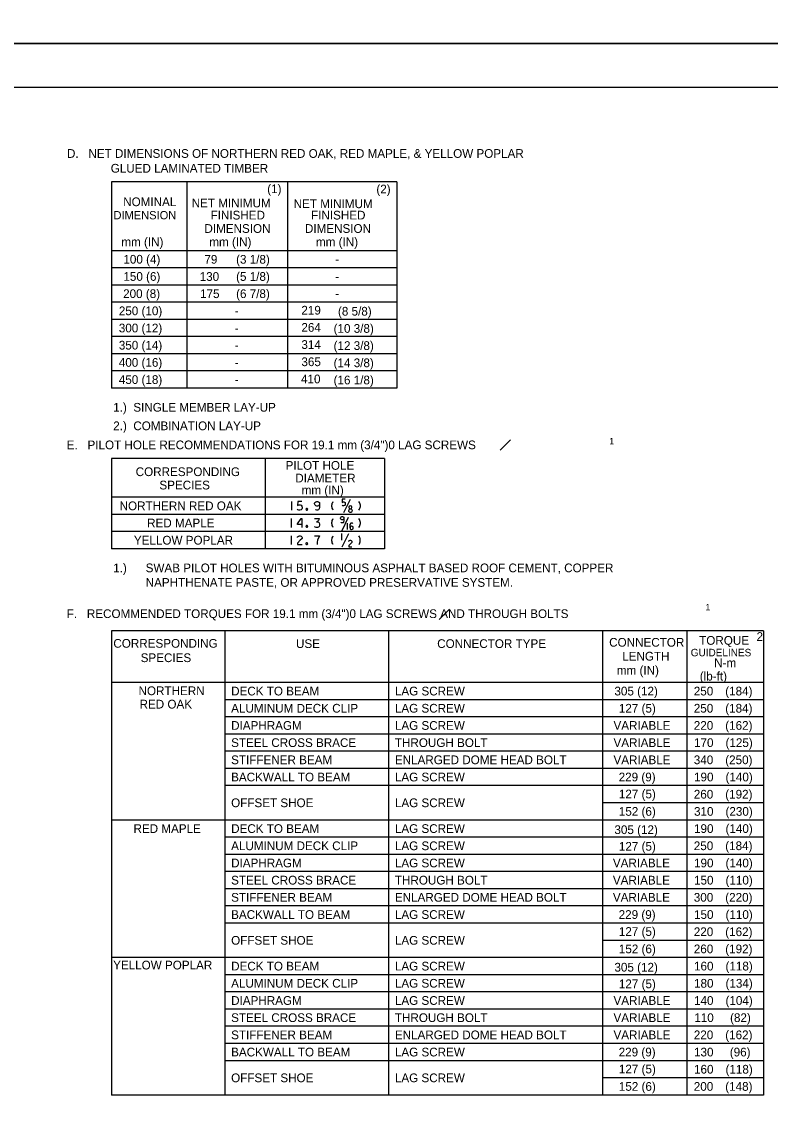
# Model space of a CAD drawing. Extents: x 637594 to 640253, y 297247 to 298527.
# Drawn here: x 639602.6 to 639860.2, y 297476.2 to 297849 of the extents above; entities that cross this region are included whole.
import ezdxf

# ---------------------------------------------------------------- set-up
doc = ezdxf.new("R2010")
doc.units = 0
doc.layers.add('2', color=7, linetype='Continuous')
doc.layers.add('PLT-BNDY', color=7, linetype='Continuous')

msp = doc.modelspace()

# ---------------------------------------------------------------- linework, layer by layer
at = {"layer": '2'}
for p, q in [((639316.46, 297826.46), (640102.46, 297826.46)), ((639731.6, 297793.9), (639633.44, 297793.9)), ((639633.44, 297793.9), (639633.44, 297722.88)), ((639659.42, 297793.9), (639659.42, 297722.88)), ((639694, 297793.9), (639694, 297722.88)), ((639731.6, 297793.9), (639731.6, 297722.88)), ((639659.42, 297787.92), (639659.42, 297746.53)), ((639731.6, 297770.18), (639633.44, 297770.18)), ((639731.6, 297764.27), (639633.44, 297764.27)), ((639731.6, 297758.36), (639633.44, 297758.36)), ((639731.6, 297752.45), (639633.44, 297752.45)), ((639731.6, 297746.53), (639633.44, 297746.53)), ((639731.6, 297740.62), (639633.44, 297740.62)), ((639731.6, 297734.71), (639633.44, 297734.71)), ((639731.6, 297728.8), (639633.44, 297728.8)), ((639731.6, 297722.88), (639633.44, 297722.88)), ((639770.79, 297705.12), (639767.24, 297701.57)), ((639727.37, 297698.69), (639633.44, 297698.69)), ((639633.44, 297698.69), (639633.44, 297667.64)), ((639686.39, 297698.69), (639686.39, 297667.64)), ((639727.37, 297698.69), (639727.37, 297667.64)), ((639727.37, 297685.38), (639633.44, 297685.38)), ((639727.37, 297679.47), (639633.44, 297679.47)), ((639727.37, 297673.55), (639633.44, 297673.55)), ((639727.37, 297667.64), (639633.44, 297667.64)), ((639749.76, 297646.92), (639746.21, 297643.37)), ((639857.76, 297639.39), (639633.44, 297639.39)), ((639633.44, 297639.39), (639633.44, 297479.75)), ((639672.46, 297639.39), (639672.46, 297479.75)), ((639728.79, 297639.39), (639728.79, 297479.75)), ((639802.42, 297639.39), (639802.42, 297479.75)), ((639831.43, 297639.39), (639831.43, 297479.75)), ((639857.76, 297639.39), (639857.76, 297479.75)), ((639857.76, 297621.65), (639633.44, 297621.65)), ((639857.76, 297615.74), (639672.46, 297615.74)), ((639857.76, 297609.83), (639672.46, 297609.83)), ((639857.76, 297603.91), (639672.46, 297603.91)), ((639857.76, 297598), (639672.46, 297598)), ((639857.76, 297592.09), (639672.46, 297592.09)), ((639857.76, 297586.18), (639672.46, 297586.18)), ((639857.76, 297580.26), (639802.42, 297580.26)), ((639857.76, 297574.35), (639633.44, 297574.35)), ((639857.76, 297568.44), (639672.46, 297568.44)), ((639857.76, 297562.53), (639672.46, 297562.53)), ((639857.76, 297556.61), (639672.46, 297556.61)), ((639857.76, 297550.7), (639672.46, 297550.7)), ((639857.76, 297544.79), (639672.46, 297544.79)), ((639857.76, 297538.87), (639672.46, 297538.87)), ((639857.76, 297532.96), (639802.42, 297532.96)), ((639857.76, 297527.05), (639633.44, 297527.05)), ((639857.76, 297521.14), (639672.46, 297521.14)), ((639857.76, 297515.22), (639672.46, 297515.22)), ((639857.76, 297509.31), (639672.46, 297509.31)), ((639857.76, 297503.4), (639672.46, 297503.4)), ((639857.76, 297497.48), (639672.46, 297497.48)), ((639857.76, 297491.57), (639672.46, 297491.57)), ((639857.76, 297485.66), (639802.42, 297485.66)), ((639857.76, 297479.75), (639633.44, 297479.75))]:
    msp.add_line(p, q, dxfattribs=at)
for points in [[(639695.46, 297680.92), (639695.46, 297683.92)], [(639699, 297683.92), (639697.53, 297683.92), (639697.42, 297682.5), (639697.98, 297682.76), (639698.39, 297682.76), (639698.76, 297682.62), (639699, 297682.36), (639699.12, 297682.01), (639699.12, 297681.63), (639699, 297681.25), (639698.76, 297681.01), (639698.24, 297680.92), (639697.89, 297680.92), (639697.63, 297681.01), (639697.42, 297681.27)], [(639705.09, 297682.83), (639704.72, 297682.46), (639704.34, 297682.31), (639704.1, 297682.29), (639703.75, 297682.46), (639703.49, 297682.69), (639703.37, 297683.07), (639703.37, 297683.19), (639703.46, 297683.59), (639703.72, 297683.8), (639704.1, 297683.92), (639704.34, 297683.92), (639704.69, 297683.8), (639704.98, 297683.59), (639705.09, 297683.19), (639705.09, 297682.31), (639705.05, 297682.01), (639704.95, 297681.35), (639704.83, 297681.13), (639704.69, 297681.01), (639704.34, 297680.92), (639704.1, 297680.92), (639703.75, 297681.01), (639703.6, 297681.13)], [(639709.77, 297680.92), (639709.58, 297681.23), (639709.44, 297681.56), (639709.35, 297681.89), (639709.3, 297682.24), (639709.3, 297682.6), (639709.35, 297682.95), (639709.44, 297683.28), (639709.58, 297683.61), (639709.77, 297683.92)], [(639713.83, 297684.68), (639712.87, 297684.68), (639712.79, 297683.61), (639713.17, 297683.83), (639713.43, 297683.83), (639713.69, 297683.71), (639713.83, 297683.52), (639713.91, 297683.26), (639713.91, 297682.97), (639713.83, 297682.69), (639713.69, 297682.5), (639713.34, 297682.43), (639713.1, 297682.43), (639712.94, 297682.5), (639712.79, 297682.69)], [(639713.41, 297680.16), (639715.65, 297684.68)], [(639718.62, 297680.92), (639718.81, 297681.23), (639718.95, 297681.56), (639719.04, 297681.89), (639719.09, 297682.24), (639719.09, 297682.6), (639719.04, 297682.95), (639718.95, 297683.28), (639718.81, 297683.61), (639718.62, 297683.92)], [(639700.98, 297681.23), (639700.96, 297681.35), (639700.89, 297681.44), (639700.79, 297681.51), (639700.68, 297681.53), (639700.56, 297681.51), (639700.46, 297681.44), (639700.39, 297681.35), (639700.37, 297681.23), (639700.39, 297681.11), (639700.46, 297681.01), (639700.56, 297680.94), (639700.68, 297680.92), (639700.79, 297680.94), (639700.89, 297681.01), (639700.96, 297681.11), (639700.98, 297681.23)], [(639715.8, 297681.42), (639716.01, 297681.49), (639716.1, 297681.61), (639716.15, 297681.87), (639716.15, 297681.98), (639716.1, 297682.27), (639715.98, 297682.34), (639715.68, 297682.41), (639715.35, 297682.34), (639715.28, 297682.27), (639715.18, 297681.98), (639715.18, 297681.87), (639715.25, 297681.61), (639715.35, 297681.49), (639715.58, 297681.42), (639715.8, 297681.42), (639716.01, 297681.27), (639716.15, 297681.06), (639716.25, 297680.83), (639716.25, 297680.73), (639716.17, 297680.42), (639716.01, 297680.23), (639715.8, 297680.16), (639715.58, 297680.16), (639715.35, 297680.23), (639715.18, 297680.42), (639715.13, 297680.71), (639715.13, 297680.83), (639715.21, 297681.06), (639715.35, 297681.27), (639715.58, 297681.42)], [(639695.45, 297675.01), (639695.45, 297678.01)], [(639699.12, 297676.05), (639697.42, 297676.05), (639697.42, 297676.17), (639698.74, 297678.01), (639698.9, 297678.01), (639698.9, 297675.01)], [(639703.37, 297678.01), (639704.95, 297678.01), (639704.86, 297677.65), (639704.69, 297677.39), (639704.46, 297677.16), (639703.98, 297676.92), (639704.34, 297676.92), (639704.71, 297676.76), (639704.95, 297676.52), (639705.07, 297676.14), (639705.07, 297675.74), (639704.95, 297675.34), (639704.69, 297675.1), (639704.34, 297675.01), (639703.93, 297675.01), (639703.58, 297675.1), (639703.37, 297675.36)], [(639709.77, 297675.01), (639709.58, 297675.31), (639709.44, 297675.64), (639709.34, 297675.98), (639709.3, 297676.33), (639709.3, 297676.68), (639709.34, 297677.04), (639709.44, 297677.37), (639709.58, 297677.7), (639709.77, 297678.01)], [(639713.43, 297677.96), (639713.2, 297677.68), (639712.93, 297677.56), (639712.77, 297677.56), (639712.53, 297677.68), (639712.37, 297677.84), (639712.3, 297678.13), (639712.3, 297678.22), (639712.37, 297678.53), (639712.53, 297678.69), (639712.77, 297678.76), (639712.93, 297678.76), (639713.17, 297678.69), (639713.36, 297678.53), (639713.43, 297678.22), (639713.43, 297677.56), (639713.38, 297677.35), (639713.34, 297676.85), (639713.27, 297676.68), (639713.17, 297676.59), (639712.93, 297676.52), (639712.77, 297676.52), (639712.53, 297676.59), (639712.46, 297676.68)], [(639712.82, 297673.97), (639715.04, 297678.48)], [(639714.71, 297674.25), (639714.71, 297676.49)], [(639716.5, 297676.35), (639716.41, 297676.42), (639716.22, 297676.49), (639716.03, 297676.49), (639715.79, 297676.42), (639715.51, 297676.05), (639715.46, 297675.69), (639715.46, 297675.29), (639715.49, 297674.96), (639715.63, 297674.51), (639715.79, 297674.32), (639716.03, 297674.25), (639716.43, 297674.35), (639716.6, 297674.51), (639716.67, 297674.79), (639716.67, 297674.94), (639716.6, 297675.15), (639716.43, 297675.36), (639716.17, 297675.43), (639716.01, 297675.46), (639715.77, 297675.36), (639715.63, 297675.15), (639715.53, 297674.79)], [(639718.62, 297675.01), (639718.8, 297675.31), (639718.95, 297675.64), (639719.04, 297675.98), (639719.09, 297676.33), (639719.09, 297676.68), (639719.04, 297677.04), (639718.95, 297677.37), (639718.8, 297677.7), (639718.62, 297678.01)], [(639695.45, 297669.09), (639695.45, 297672.09)], [(639697.41, 297671.48), (639697.5, 297671.76), (639697.76, 297672), (639698.12, 297672.09), (639698.38, 297672.09), (639698.73, 297672), (639698.99, 297671.74), (639699.11, 297671.48), (639699.11, 297671.22), (639699.01, 297671.01), (639698.42, 297670.56), (639697.5, 297669.61), (639697.41, 297669.38), (639697.41, 297669.09), (639699.11, 297669.09)], [(639700.98, 297675.31), (639700.96, 297675.43), (639700.89, 297675.53), (639700.79, 297675.6), (639700.67, 297675.62), (639700.56, 297675.6), (639700.46, 297675.53), (639700.39, 297675.43), (639700.37, 297675.31), (639700.39, 297675.2), (639700.46, 297675.1), (639700.56, 297675.03), (639700.67, 297675.01), (639700.79, 297675.03), (639700.89, 297675.1), (639700.96, 297675.2), (639700.98, 297675.31)], [(639703.36, 297672.09), (639705.06, 297672.09), (639705.06, 297671.98), (639704.54, 297671.22), (639704.33, 297670.63), (639704.21, 297669.9), (639704.21, 297669.09)], [(639709.76, 297669.09), (639709.57, 297669.4), (639709.43, 297669.73), (639709.34, 297670.06), (639709.29, 297670.42), (639709.29, 297670.77), (639709.34, 297671.13), (639709.43, 297671.46), (639709.57, 297671.79), (639709.76, 297672.09)], [(639712.76, 297670.61), (639712.76, 297672.85)], [(639712.86, 297668.34), (639715.1, 297672.85)], [(639718.61, 297669.09), (639718.8, 297669.4), (639718.94, 297669.73), (639719.03, 297670.06), (639719.08, 297670.42), (639719.08, 297670.77), (639719.03, 297671.13), (639718.94, 297671.46), (639718.8, 297671.79), (639718.61, 297672.09)], [(639700.97, 297669.4), (639700.95, 297669.52), (639700.88, 297669.61), (639700.78, 297669.68), (639700.67, 297669.71), (639700.55, 297669.68), (639700.45, 297669.61), (639700.38, 297669.52), (639700.36, 297669.4), (639700.38, 297669.28), (639700.45, 297669.19), (639700.55, 297669.12), (639700.67, 297669.09), (639700.78, 297669.12), (639700.88, 297669.19), (639700.95, 297669.28), (639700.97, 297669.4)], [(639715.1, 297670.13), (639715.15, 297670.35), (639715.31, 297670.51), (639715.57, 297670.58), (639715.74, 297670.58), (639715.97, 297670.51), (639716.14, 297670.32), (639716.21, 297670.13), (639716.21, 297669.94), (639716.14, 297669.78), (639715.76, 297669.45), (639715.15, 297668.74), (639715.1, 297668.55), (639715.1, 297668.34), (639716.21, 297668.34)]]:
    msp.add_lwpolyline(points, dxfattribs=at)
at = {"layer": 'PLT-BNDY'}
for points in [[(639276.46, 298435.46), (640117.46, 298435.46), (640117.46, 297841.46), (639276.46, 297841.46)], [(639276.46, 297841.46), (640117.46, 297841.46), (640117.46, 297247.46), (639276.46, 297247.46)]]:
    msp.add_lwpolyline(points, close=True, dxfattribs=at)

# ---------------------------------------------------------------- texts
at = {"layer": '2'}
for s, height, p in [('D.   NET DIMENSIONS OF NORTHERN RED OAK, RED MAPLE, & YELLOW POPLAR', 3.0001, (639618.16, 297802.12)), ('GLUED LAMINATED TIMBER', 3.0001, (639633.2, 297797.03)), ('(1)', 3, (639687.05, 297789.97)), ('(2)', 3, (639724.6, 297789.88)), ('NOMINAL', 3, (639637.5, 297785.5)), ('NET MINIMUM', 3.0001, (639661.06, 297785.08)), ('NET MINIMUM', 3.0001, (639696.15, 297784.82)), ('FINISHED', 3, (639667.55, 297780.91)), ('FINISHED', 3, (639702.13, 297780.91)), ('DIMENSION', 2.85, (639634.15, 297780.97)), ('DIMENSION', 3, (639665.44, 297776.31)), ('DIMENSION', 3, (639700.02, 297776.31)), ('mm (IN)', 3, (639636.85, 297771.72)), ('mm (IN)', 3, (639667.12, 297771.72)), ('mm (IN)', 3, (639703.82, 297771.72)), ('100 (4)', 3, (639637.56, 297765.73)), ('79', 3, (639665.43, 297765.71)), ('(3 1/8)', 3, (639676.34, 297765.71)), ('-', 3, (639710.43, 297765.73)), ('150 (6)', 3, (639637.56, 297759.82)), ('130', 3, (639663.81, 297759.8)), ('(5 1/8)', 3, (639676.34, 297759.8)), ('-', 3, (639710.43, 297759.82)), ('200 (8)', 3, (639637.47, 297753.9)), ('175', 3, (639663.94, 297753.89)), ('(6 7/8)', 3, (639676.34, 297753.89)), ('-', 3, (639710.43, 297753.9)), ('250 (10)', 3, (639635.99, 297747.99)), ('219', 3, (639698.8, 297748.21)), ('(8 5/8)', 3, (639711.39, 297747.85)), ('-', 3, (639675.85, 297747.99)), ('300 (12)', 3, (639635.99, 297742.08)), ('-', 3, (639675.85, 297742.08)), ('264', 3, (639698.81, 297742.3)), ('(10 3/8)', 3, (639709.89, 297741.94)), ('350 (14)', 3, (639635.99, 297736.17)), ('314', 3, (639698.81, 297736.39)), ('(12 3/8)', 3, (639709.89, 297736.03)), ('-', 3, (639675.85, 297736.17)), ('400 (16)', 3, (639635.99, 297730.25)), ('365', 3, (639698.81, 297730.47)), ('(14 3/8)', 3, (639709.89, 297730.11)), ('-', 3, (639675.85, 297730.25)), ('450 (18)', 3, (639635.99, 297724.34)), ('-', 3, (639675.85, 297724.34)), ('410', 3, (639698.68, 297724.56)), ('(16 1/8)', 3, (639709.89, 297724.2)), ('1.)  SINGLE MEMBER LAY-UP', 3.0001, (639634.06, 297714.81)), ('2.)  COMBINATION LAY-UP', 3.0001, (639634.06, 297708.44)), ('1', 2.25, (639804.72, 297703.55)), ('E.   PILOT HOLE RECOMMENDATIONS FOR 19.1 mm (3/4")0 LAG SCREWS', 3.0001, (639618.08, 297701.88)), ('CORRESPONDING', 3.0001, (639641.79, 297692.65)), ('PILOT HOLE', 3, (639693.36, 297694.82)), ('SPECIES', 3, (639649.94, 297688.06)), ('DIAMETER', 3, (639696.71, 297690.46)), ('mm (IN)', 3, (639698.89, 297686.36)), ('NORTHERN RED OAK', 3.0001, (639636.26, 297680.92)), ('RED MAPLE', 3, (639645.72, 297675.01)), ('YELLOW POPLAR', 3.0001, (639641.17, 297669.1)), ('1.)', 3, (639634.06, 297659.57)), ('SWAB PILOT HOLES WITH BITUMINOUS ASPHALT BASED ROOF CEMENT, COPPER', 3.0001, (639645.22, 297659.57)), ('NAPHTHENATE PASTE, OR APPROVED PRESERVATIVE SYSTEM.', 3.0001, (639645.22, 297654.57)), ('F.   RECOMMENDED TORQUES FOR 19.1 mm (3/4")0 LAG SCREWS AND THROUGH BOLTS', 3.0001, (639618.08, 297643.82)), ('1', 2.25, (639837.83, 297646.42)), ('2', 3, (639855.4, 297635.95)), ('CORRESPONDING', 3.0001, (639634.11, 297633.61)), ('USE', 3, (639696.95, 297633.52)), ('CONNECTOR TYPE', 3.0001, (639745.53, 297633.52)), ('CONNECTOR', 3, (639804.7, 297633.97)), ('TORQUE', 3, (639835.67, 297634.63)), ('SPECIES', 3, (639643.5, 297628.67)), ('LENGTH', 3, (639809.19, 297629.19)), ('GUIDELINES', 2.572, (639832.76, 297630.66)), ('mm (IN)', 3, (639807.34, 297624.34)), ('N-m', 3, (639840.84, 297626.91)), ('(lb-ft)', 3, (639835.88, 297622.33)), ('NORTHERN', 3, (639642.78, 297617.3)), ('DECK TO BEAM', 3.0001, (639674.63, 297617.2)), ('LAG SCREW', 3, (639730.97, 297617.2)), ('305 (12)', 3, (639806.51, 297617.2)), ('250', 3, (639833.82, 297617.2)), ('(184)', 3, (639844.64, 297617.2)), ('RED OAK', 3, (639643.12, 297612.7)), ('ALUMINUM DECK CLIP', 3.0001, (639674.63, 297611.29)), ('LAG SCREW', 3, (639730.97, 297611.29)), ('127 (5)', 3, (639808.04, 297611.29)), ('250', 3, (639833.82, 297611.29)), ('(184)', 3, (639844.64, 297611.29)), ('DIAPHRAGM', 3, (639674.63, 297605.37)), ('LAG SCREW', 3, (639730.97, 297605.37)), ('VARIABLE', 3, (639806.19, 297605.38)), ('220', 3, (639833.82, 297605.38)), ('(162)', 3, (639844.64, 297605.38)), ('STEEL CROSS BRACE', 3.0001, (639674.63, 297599.46)), ('THROUGH BOLT', 3.0001, (639730.97, 297599.46)), ('VARIABLE', 3, (639806.19, 297599.46)), ('170', 3, (639833.9, 297599.46)), ('(125)', 3, (639844.73, 297599.46)), ('STIFFENER BEAM', 3.0001, (639674.63, 297593.55)), ('ENLARGED DOME HEAD BOLT', 3.0001, (639730.97, 297593.55)), ('VARIABLE', 3, (639806.19, 297593.55)), ('340', 3, (639833.82, 297593.55)), ('(250)', 3, (639844.64, 297593.55)), ('BACKWALL TO BEAM', 3.0001, (639674.63, 297587.63)), ('LAG SCREW', 3, (639730.97, 297587.63)), ('229 (9)', 3, (639807.97, 297587.64)), ('190', 3, (639833.9, 297587.64)), ('(140)', 3, (639844.73, 297587.64)), ('127 (5)', 3, (639808.04, 297581.8)), ('260', 3, (639833.82, 297581.72)), ('(192)', 3, (639844.64, 297581.72)), ('OFFSET SHOE', 3.0001, (639674.63, 297578.77)), ('LAG SCREW', 3, (639730.97, 297578.77)), ('152 (6)', 3, (639808.03, 297575.81)), ('(230)', 3, (639844.73, 297575.81)), ('310', 3, (639833.9, 297575.81)), ('RED MAPLE', 3, (639641.03, 297569.9)), ('DECK TO BEAM', 3.0001, (639674.63, 297569.9)), ('LAG SCREW', 3, (639730.97, 297569.9)), ('305 (12)', 3, (639806.51, 297569.52)), ('190', 3, (639833.9, 297569.9)), ('(140)', 3, (639844.73, 297569.9)), ('ALUMINUM DECK CLIP', 3.0001, (639674.63, 297563.98)), ('LAG SCREW', 3, (639730.97, 297563.98)), ('127 (5)', 3, (639808.04, 297563.8)), ('250', 3, (639833.82, 297563.99)), ('(184)', 3, (639844.64, 297563.99)), ('DIAPHRAGM', 3, (639674.63, 297558.07)), ('LAG SCREW', 3, (639730.97, 297558.07)), ('VARIABLE', 3, (639805.98, 297558.07)), ('190', 3, (639833.9, 297558.07)), ('(140)', 3, (639844.73, 297558.07)), ('STEEL CROSS BRACE', 3.0001, (639674.63, 297552.16)), ('THROUGH BOLT', 3.0001, (639730.97, 297552.16)), ('VARIABLE', 3, (639805.98, 297552.16)), ('150', 3, (639833.9, 297552.16)), ('(110)', 3, (639844.73, 297552.16)), ('STIFFENER BEAM', 3.0001, (639674.63, 297546.25)), ('ENLARGED DOME HEAD BOLT', 3.0001, (639730.97, 297546.25)), ('VARIABLE', 3, (639805.98, 297546.25)), ('300', 3, (639833.82, 297546.25)), ('(220)', 3, (639844.64, 297546.25)), ('BACKWALL TO BEAM', 3.0001, (639674.63, 297540.33)), ('LAG SCREW', 3, (639730.97, 297540.33)), ('229 (9)', 3, (639807.97, 297540.33)), ('150', 3, (639833.9, 297540.33)), ('(110)', 3, (639844.73, 297540.33)), ('OFFSET SHOE', 3.0001, (639674.63, 297531.46)), ('LAG SCREW', 3, (639730.97, 297531.46)), ('127 (5)', 3, (639808.04, 297534.49)), ('220', 3, (639833.82, 297534.42)), ('(162)', 3, (639844.64, 297534.42)), ('152 (6)', 3, (639808.03, 297528.51)), ('260', 3, (639833.82, 297528.51)), ('(192)', 3, (639844.64, 297528.51)), ('YELLOW POPLAR', 3.0001, (639634.03, 297522.95)), ('DECK TO BEAM', 3.0001, (639674.63, 297522.59)), ('LAG SCREW', 3, (639730.97, 297522.59)), ('305 (12)', 3, (639806.51, 297522.21)), ('160', 3, (639833.9, 297522.6)), ('(118)', 3, (639844.73, 297522.6)), ('ALUMINUM DECK CLIP', 3.0001, (639674.63, 297516.68)), ('LAG SCREW', 3, (639730.97, 297516.68)), ('127 (5)', 3, (639808.04, 297516.49)), ('180', 3, (639833.9, 297516.68)), ('(134)', 3, (639844.73, 297516.68)), ('DIAPHRAGM', 3, (639674.63, 297510.77)), ('LAG SCREW', 3, (639730.97, 297510.77)), ('VARIABLE', 3, (639806.19, 297510.77)), ('140', 3, (639833.9, 297510.77)), ('(104)', 3, (639844.73, 297510.77)), ('STEEL CROSS BRACE', 3.0001, (639674.63, 297504.86)), ('THROUGH BOLT', 3.0001, (639730.97, 297504.86)), ('VARIABLE', 3, (639806.19, 297504.86)), ('110', 3, (639833.99, 297504.86)), ('(82)', 3, (639846.3, 297504.86)), ('STIFFENER BEAM', 3.0001, (639674.63, 297498.94)), ('ENLARGED DOME HEAD BOLT', 3.0001, (639730.97, 297498.94)), ('VARIABLE', 3, (639806.19, 297498.95)), ('220', 3, (639833.82, 297498.95)), ('(162)', 3, (639844.64, 297498.95)), ('BACKWALL TO BEAM', 3.0001, (639674.63, 297493.03)), ('LAG SCREW', 3, (639730.97, 297493.03)), ('229 (9)', 3, (639807.97, 297493.03)), ('130', 3, (639833.9, 297493.03)), ('(96)', 3, (639846.21, 297493.03)), ('127 (5)', 3, (639808.04, 297487.19)), ('160', 3, (639833.9, 297487.12)), ('(118)', 3, (639844.73, 297487.12)), ('OFFSET SHOE', 3.0001, (639674.63, 297484.16)), ('LAG SCREW', 3, (639730.97, 297484.16)), ('152 (6)', 3, (639808.03, 297481.21)), ('200', 3, (639833.82, 297481.21)), ('(148)', 3, (639844.64, 297481.21))]:
    msp.add_text(s, height=height, dxfattribs=at).set_placement(p)

doc.saveas('drawing.dxf')
